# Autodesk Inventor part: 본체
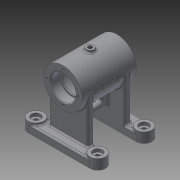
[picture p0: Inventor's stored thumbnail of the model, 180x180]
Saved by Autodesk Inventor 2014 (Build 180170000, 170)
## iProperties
Created: 2015-11
Part Number: 본체
Material: 일반
Document SubType Name: Modeling
Designer: basic
Density: 1 g/cm^3
Appearance: 기본값
Author: basic
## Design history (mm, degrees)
sketch "스케치1"
  geometry: C1 r 25 at (0, 0); 1 further point
  constraints: 1 centre point, 1 coincident
  dimensions: "d0" = 50 diameter of C1
extrude "돌출1" new body sketch "스케치1" stored distance "d1" = 70; taper "d2" = 0 deg
sketch "스케치2"
  geometry: C1 r 25 at (0, 0) reference; C2 r 16 at (0, 0)
  constraints: 1 centre point, 1 coincident
  dimensions: "d3" = 32 diameter of C2
extrude "돌출2" cut sketch "스케치2" distance "d4" = 12; taper "d5" = 0 deg
sketch "스케치3"
  geometry: C1 r 21 at (0, 0); 1 further point
  constraints: 1 centre point, 1 coincident
  dimensions: "d6" = 42 diameter of C1
extrude "돌출3" cut sketch "스케치3" stored distance "d7" = 42; taper "d8" = 0 deg
sketch "스케치4"
  geometry: C1 r 16 at (0, 0) reference; C2 r 14 at (0, 0)
  constraints: 1 centre point, 1 coincident
  dimensions: "d9" = 28 diameter of C2
extrude "돌출4" cut sketch "스케치4" stored distance "d10" = 42; taper "d11" = 0 deg
node "작업 평면1"
sketch "스케치5"
  geometry: L1 (-40, -30)-(40, -30); L2 (-40, -20)-(40, -20); L3 (40, -40)-(-40, -40); A1 r 10 centre (-40, -30) between (-40, -20) and (-40, -40); A2 r 10 centre (40, -30) between (40, -40) and (40, -20); 3 further points
  constraints: 8 end point, 4 point on circle, 4 tangent, 2 centre point, 2 midpoint, 1 horizontal, 1 parallel, 1 vertical alignment
  dimensions: "d13" = 80 distance of L1.start L1.end; "d14" = 20 distance between parallel lines of L2 L3; "d15" = 40 distance from line of point (0, 0) L3
extrude "돌출5" join sketch "스케치5" distance "d16" = 10; taper "d17" = 0 deg
sketch "스케치6"
  geometry: L1 (40, -20)-(-40, -20) reference; L2 (-25, -20)-(25, -20); L3 (25, -20)-(25, -28); L4 (25, -28)-(-25, -28); L5 (-25, -28)-(-25, -20); 2 further points
  constraints: 8 end point, 2 midpoint, 2 parallel, 1 horizontal, 1 perpendicular
  dimensions: "d18" = 8 distance between parallel lines of L4 L2; "d19" = 50 distance of L3.end L4.end
extrude "돌출6" join sketch "스케치6" stored distance "d20" = 10; taper "d21" = 0 deg
sketch "스케치7"
  geometry: C1 r 10 at (40, -30); A1 r 10 centre (-40, -30) between (-40, -20) and (-40, -40) reference; A2 r 10 centre (40, -30) between (40, -40) and (40, -20) reference; 2 further points
  constraints: 2 coincident, 1 centre point, 1 concentric, 1 vertical alignment, 2 other
extrude "돌출7" join sketch "스케치7" distance "d22" = 3; taper "d23" = 0 deg
sketch "스케치8"
  geometry: C1 r 10 at (0, 0) reference; 2 further points
  constraints: 1 coincident
hole "구멍1" sketch "스케치8" at (0, 0) diameter "d24" = 6; stored, may be unused: countersink angle "d28" = 90 deg, drill point angle "d30" = 118 deg; dims "d25" = 6, "d26" = 12, "d27" = 4, "d29" = 8
node "작업 평면3"
  node "작업 평면2"
sketch "스케치9"
  geometry: L1 (25, 28)-(25, 20) reference; L2 (25, 20)-(-25, 20) reference; L3 (-25, 20)-(-25, 28) reference; L4 (-25, 28)-(25, 28) reference; L5 (25, -20)-(25, -28) reference; L6 (25, -28)-(-25, -28) reference; L7 (-25, -28)-(-25, -20) reference; L8 (-25, -20)-(25, -20) reference; L9 (4, -20)-(-4, -20); L10 (-4, -20)-(-4, 20); L11 (-4, 20)-(4, 20); L12 (4, 20)-(4, -20); 3 further points
  constraints: 8 end point, 4 midpoint, 2 parallel, 1 horizontal, 1 perpendicular
  dimensions: "d32" = 8 distance between parallel lines of L10 L12
extrude "돌출8" join sketch "스케치9" stored distance "d33" = 3; taper "d34" = 0 deg
sketch "스케치10"
  geometry: L1 (-20.322, 0)-(-20.322, 40) reference; L2 (-10, 12)-(-10, 28); L3 (-13.5, 12)-(-13.5, 28); L4 (-6.5, 28)-(-6.5, 12); L5 (23, 60)-(23, 40) reference; A1 r 3.5 centre (-10, 12) between (-13.5, 12) and (-6.5, 12); A2 r 3.5 centre (-10, 28) between (-6.5, 28) and (-13.5, 28); 2 further points
  constraints: 8 end point, 4 point on circle, 4 tangent, 2 centre point, 2 parallel, 1 horizontal alignment, 1 midpoint
  dimensions: "d35" = 33 distance from line of L5 point (-10, 20); "d36" = 3.5 radius of A2; "d37" = 23 dimension on A2 A1
extrude "돌출9" cut sketch "스케치10" stored distance "d38" = 3; taper "d39" = 0 deg
sketch "스케치11"
  geometry: C1 r 16 at (0, 0) reference; 1 further point
  constraints: 1 horizontal alignment
  dimensions: "d40" = 20 distance of C1.centre point (20, 0)
hole "구멍2" sketch "스케치11" at (20, 0) diameter "d41" = 3.242; stored, may be unused: countersink angle "d45" = 90 deg, drill point angle "d47" = 118 deg; dims "d42" = 8, "d43" = 12, "d44" = 4, "d46" = 10
node "작업 평면4"
sketch "스케치12"
  geometry: C1 r 5 at (0, 0); 1 further point
  constraints: 1 centre point, 1 coincident
  dimensions: "d52" = 10 diameter of C1
extrude "돌출10" join sketch "스케치12" stored distance "d53" = 3; taper "d54" = 0 deg
sketch "스케치13"
  geometry: C1 r 5 at (0, 0) reference; 1 further point
  constraints: 1 coincident
hole "구멍3" sketch "스케치13" at (0, 0) diameter "d55" = 5.188; stored, may be unused: countersink angle "d59" = 90 deg, drill point angle "d61" = 118 deg; dims "d56" = 10, "d57" = 12, "d58" = 4, "d60" = 10
sketch "스케치14"
  geometry: L1 (0, 0)-(0, -14); L2 (0, 0)-(-12.5, 21.651); A1 r 25 centre (0, 0) between (-4, 24.678) and (-25, 0) reference; 1 further point
  constraints: 4 end point, 1 point on circle, 1 vertical, 1 vertical alignment, 1 other
  dimensions: "d65" = 30 deg angle of L2 L1
node "작업 평면6"
  node "작업 평면5"
sketch "스케치15"
  geometry: C1 r 6 at (0, 0); 1 further point
  constraints: 1 centre point, 1 coincident
  dimensions: "d67" = 12 diameter of C1
extrude "돌출11" join sketch "스케치15" stored distance "d68" = 3; taper "d69" = 0 deg
sketch "스케치16"
  geometry: C1 r 6 at (0, 0) reference; 1 further point
  constraints: 1 coincident
hole "구멍4" sketch "스케치16" at (0, 0) diameter "d70" = 5.188; stored, may be unused: countersink angle "d74" = 90 deg, drill point angle "d76" = 118 deg; dims "d71" = 10, "d72" = 12, "d73" = 4, "d75" = 10
fillet "모깎기1" dims "d77" = 3
fillet "모깎기2" dims "d78" = 2
fillet "모깎기3" dims "d79" = 0.3
fillet "모깎기4" dims "d80" = 2
fillet "모깎기5" dims "d81" = 2
fillet "모깎기6" dims "d82" = 2
fillet "모깎기7" dims "d83" = 2
fillet "모깎기8" dims "d84" = 2
fillet "모깎기9" dims "d85" = 2
fillet "모깎기10" dims "d86" = 2
fillet "모깎기11" dims "d87" = 2
chamfer "모따기1" distance "d88" = 1; stored, may be unused: second distance "d89" = 2, angle "d90" = 45 deg
chamfer "모따기2" distance "d91" = 1; stored, may be unused: second distance "d92" = 2, angle "d93" = 45 deg
node "작업 평면7"
sketch "스케치17"
  geometry: L1 (35, -25)-(35, 25) reference; L2 (35, -25)-(-35, -25) reference; 2 further points
  constraints: 1 other
  dimensions: "d95" = 35 distance from line of point (0, 0) L1; "d96" = 25 distance from line of point (0, 0) L2
feature "엠보싱1" sketch "스케치17" dims "d97" = 0.5, "d98" = 0
fillet "모깎기12" dims "d99" = 2
node "솔리드1"
mirror "대칭1"
mirror "대칭2"
mirror "대칭3"
pattern_circular "원형 패턴1" dims angle "d49" = 360 deg
mirror "대칭4"
node "절단 모서리 투영1"
other parameters: "d12" = 68, "d51" = -28, "d66" = 3, "d94" = -25
